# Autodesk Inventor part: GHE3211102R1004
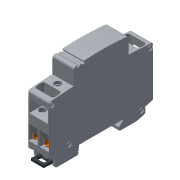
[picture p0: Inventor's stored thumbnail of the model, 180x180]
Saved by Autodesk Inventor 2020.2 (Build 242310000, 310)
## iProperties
Manager: www.cadconsulting.pl
Company: Fabian Stasiak CAD Consulting
GlobalPropertyList: <PropertyList/>
Created: 2015-10
Part Number: GHE3211102R1004
Material: Ogólny
Document SubType Name: Modeling
Designer: F.Stasiak
Density: 1 g/cm^3
Appearance: Domyślna
Catalog Web Link: www.expertbooks.pl
Sending System: Autodesk Inventor 2016
Preprocessor: ST-DEVELOPER v16.1
Title: C:\Zbiór ćwiczeń AI 2016 KPS ROB\Wiązki\ABB\ESB_20.20.stp
Author: F.Stasiak
Subject: Zbiór ćwiczeń. Autodesk Inventor 2020. Kurs Professional
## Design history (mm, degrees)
feature "Bryła1"
node "Oś konstrukcyjna1"
node "Oś konstrukcyjna2"
node "Oś konstrukcyjna3"
node "Oś konstrukcyjna4"
node "Oś konstrukcyjna6"
node "Oś konstrukcyjna5"
node "Płaszczyzna konstrukcyjna1"
node "Płaszczyzna konstrukcyjna2"
node "Punkt konstrukcyjny1"
node "Punkt konstrukcyjny2"
node "Punkt konstrukcyjny3"
node "Punkt konstrukcyjny4"
node "Punkt konstrukcyjny5"
node "Punkt konstrukcyjny6"
node "A2"
node "2"
node "4"
node "A1"
node "1"
node "3"
node "Bryła2"
